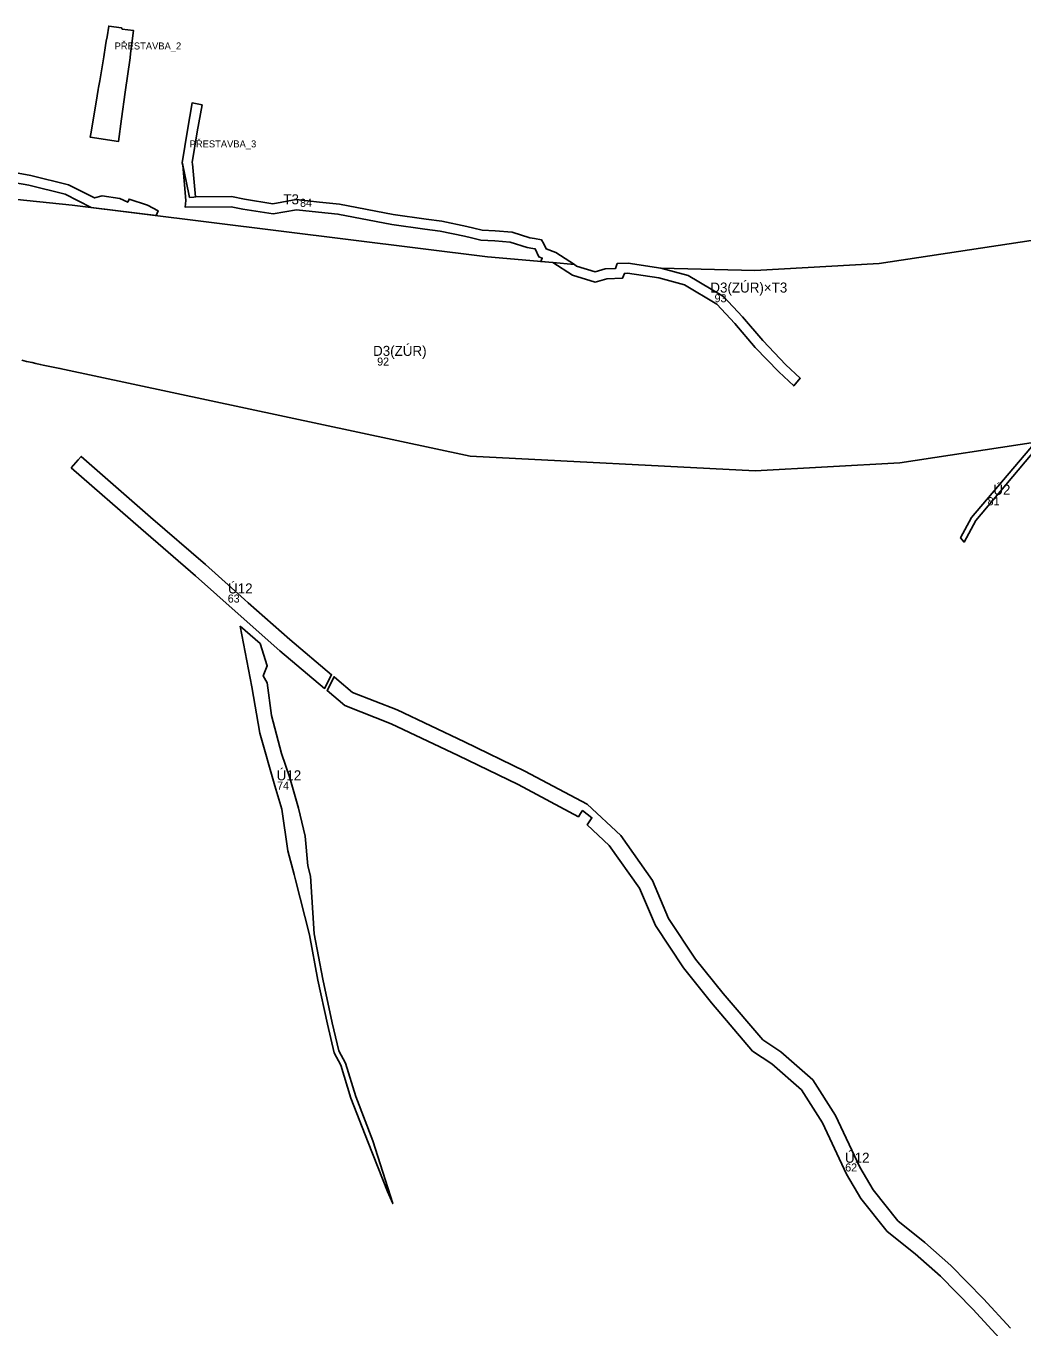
# Model space of a CAD drawing. Extents: x -521621 to -516857, y -1190025 to -1185894.
# Drawn here: x -519468 to -518471, y -1188636 to -1187334 of the extents above; entities that cross this region are included whole.
import ezdxf

# ---------------------------------------------------------------- set-up
doc = ezdxf.new("R2010")
doc.units = 0
for name, color, linetype in [('prestavba_n', 7, 'Continuous'), ('VPO_id', 7, 'Continuous'), ('VPO_n', 7, 'Continuous'), ('VPS_id', 7, 'Continuous'), ('VPS_n', 7, 'Continuous')]:
    doc.layers.add(name, color=color, linetype=linetype)

msp = doc.modelspace()

# ---------------------------------------------------------------- linework, layer by layer
at = {"layer": 'prestavba_n'}
for points in [[(-519368.5, -1187400.5), (-519363.8, -1187366.1), (-519363.3, -1187362), (-519363, -1187359.7), (-519360.2, -1187339), (-519371.6, -1187337.6), (-519372.3, -1187336.4), (-519385.1, -1187334.5), (-519386.8, -1187345.3), (-519387.5, -1187349.5), (-519388.2, -1187354), (-519390, -1187365.2), (-519391.3, -1187373.2), (-519394.1, -1187389.3), (-519395.2, -1187396), (-519395.6, -1187397.9), (-519396.7, -1187404.2), (-519402.6, -1187440.6), (-519403.5, -1187445.6), (-519375.2, -1187449.8), (-519372.2, -1187427.2), (-519368.5, -1187400.5)], [(-519311.7, -1187471.1), (-519311.4, -1187472.4), (-519311.1, -1187473.6), (-519307.7, -1187489.7), (-519304.3, -1187505.8), (-519299.9, -1187505.5), (-519298.2, -1187505.3), (-519301.2, -1187472.1), (-519301.5, -1187470.9), (-519296.5, -1187440.4), (-519291.8, -1187413.4), (-519301.7, -1187411.4), (-519306.3, -1187438.7), (-519311.7, -1187471.1)]]:
    msp.add_lwpolyline(points, dxfattribs=at)
at = {"layer": 'VPO_n'}
for points in [[(-518451.1, -1187749.3), (-518518.3, -1187828.7), (-518530, -1187850.3), (-518533.4, -1187846), (-518522.5, -1187825.9), (-518458.6, -1187750.5)], [(-519422.5, -1187776), (-519415.6, -1187768.2), (-519412.6, -1187764.7), (-519343.3, -1187825.6), (-519288.3, -1187872.8), (-519249.5, -1187907.6), (-519245.6, -1187911), (-519204.1, -1187947.8), (-519162.2, -1187983), (-519169.2, -1187996.7), (-519213.9, -1187959.1), (-519255.6, -1187922.2), (-519298.2, -1187884.1), (-519353.1, -1187836.9)], [(-519253.8, -1187934.5), (-519233.6, -1187951.8), (-519226.6, -1187973.9), (-519230.7, -1187984), (-519226.7, -1187990.9), (-519222.4, -1188023.6), (-519212.2, -1188061.6), (-519204, -1188086.1), (-519195.2, -1188116.4), (-519188.6, -1188144.5), (-519186.1, -1188173.9), (-519183.4, -1188184.3), (-519179.6, -1188242), (-519171.1, -1188287.2), (-519161.6, -1188331.1), (-519155.1, -1188358.9), (-519148.3, -1188371.3), (-519138.1, -1188404.6), (-519120.9, -1188448.8), (-519101.2, -1188511.7), (-519106.4, -1188499.6), (-519125.6, -1188450.6), (-519142.9, -1188406.3), (-519152.9, -1188373.2), (-519159.8, -1188360.8), (-519166.5, -1188332.2), (-519176, -1188288.2), (-519184.4, -1188243.1), (-519198.2, -1188188.1), (-519199.6, -1188182.6), (-519205.9, -1188159.1), (-519212.1, -1188117.2), (-519218.9, -1188094), (-519234, -1188041.5), (-519242, -1187995.2)]]:
    msp.add_lwpolyline(points, close=True, dxfattribs=at)
msp.add_lwpolyline([(-518494.6, -1188646.3), (-518521.3, -1188617.2), (-518553.6, -1188584.3), (-518578.9, -1188561.9), (-518606.8, -1188539.5), (-518633, -1188506.5), (-518647.5, -1188482.3), (-518671.6, -1188430.9), (-518692.6, -1188397.9), (-518722.2, -1188371.9), (-518741.4, -1188359.3), (-518782.4, -1188311.1), (-518810.5, -1188276.1), (-518838.6, -1188233.7), (-518854.5, -1188196.2), (-518884.6, -1188153.7), (-518906.7, -1188133.1), (-518902, -1188126), (-518906.7, -1188122.4), (-518911.4, -1188118.8), (-518913.4, -1188121.8), (-518915.5, -1188124.9), (-518975.8, -1188092.8), (-519035.8, -1188063.6), (-519102.8, -1188032), (-519149.1, -1188013.6), (-519166.7, -1187998.8), (-519159.8, -1187985), (-519159.6, -1187985.2), (-519157, -1187987.3), (-519141.3, -1188000.6), (-519096.8, -1188018.2), (-519029.3, -1188050.1), (-518969, -1188079.4), (-518906.7, -1188112.5), (-518873.2, -1188143.8), (-518841.3, -1188188.8), (-518825.3, -1188226.5), (-518798.4, -1188267.3), (-518770.9, -1188301.6), (-518731.3, -1188347.9), (-518713.1, -1188360), (-518681.1, -1188388), (-518658.4, -1188423.7), (-518634.3, -1188475.2), (-518620.7, -1188498), (-518596.1, -1188528.9), (-518569.2, -1188550.4), (-518543.2, -1188573.4), (-518510.4, -1188606.8), (-518483.5, -1188636.3)], dxfattribs=at)
at = {"layer": 'VPS_n'}
for points in [[(-519306.3, -1187438.7), (-519301.7, -1187411.4), (-519291.8, -1187413.4), (-519296.5, -1187440.4), (-519301.5, -1187470.9), (-519301.2, -1187472.1), (-519298.2, -1187505.3), (-519262.5, -1187504.9), (-519249.3, -1187507.6), (-519220.9, -1187512.2), (-519197.7, -1187508), (-519174.4, -1187510.5), (-519154.5, -1187512.6), (-519100.6, -1187523), (-519067.6, -1187527.6), (-519052.2, -1187529.7), (-519027.2, -1187534.9), (-519020.2, -1187536.4), (-519011.6, -1187538.6), (-518998.6, -1187539.3), (-518981.7, -1187540.5), (-518964.2, -1187546.2), (-518959.5, -1187546.9), (-518952.3, -1187548.3), (-518950, -1187552.2), (-518947.7, -1187557.3), (-518938.1, -1187561), (-518919.5, -1187573), (-518941, -1187571), (-518953.1, -1187569.9), (-518951.6, -1187566.5), (-518955.2, -1187565.1), (-518958.7, -1187557.3), (-518961.2, -1187556.8), (-518966.6, -1187556), (-518983.6, -1187550.4), (-518999.2, -1187549.3), (-519013.1, -1187548.5), (-519022.5, -1187546.1), (-519029.3, -1187544.6), (-519053.8, -1187539.6), (-519069, -1187537.5), (-519102.2, -1187532.8), (-519155.9, -1187522.5), (-519175.4, -1187520.4), (-519197.3, -1187518.1), (-519220.8, -1187522.3), (-519251.1, -1187517.4), (-519262.7, -1187515.1), (-519308.7, -1187515.4), (-519307.9, -1187508.8), (-519311.1, -1187473.6), (-519311.7, -1187471.1)], [(-518941, -1187571), (-518919.5, -1187573), (-518917.3, -1187574.4), (-518898.7, -1187580.1), (-518888.6, -1187577.2), (-518878.4, -1187576.7), (-518876.6, -1187571.9), (-518865.7, -1187571.6), (-518833.1, -1187576.5), (-518805.7, -1187584), (-518770.6, -1187604.7), (-518751.6, -1187625.3), (-518731.3, -1187649), (-518708, -1187673), (-518693.8, -1187686.5), (-518700.2, -1187694.3), (-518715.1, -1187680.2), (-518738.7, -1187655.7), (-518759, -1187631.9), (-518777, -1187612.5), (-518809.6, -1187593.3), (-518835.2, -1187586.3), (-518866.3, -1187581.6), (-518869.6, -1187581.7), (-518871.3, -1187586.4), (-518887, -1187587.1), (-518898.8, -1187590.5), (-518921.5, -1187583.6)]]:
    msp.add_lwpolyline(points, close=True, dxfattribs=at)
for points in [[(-519790.9, -1187475.7), (-519421.5, -1187513.5), (-519006.3, -1187565.1), (-518941, -1187571), (-518921.5, -1187583.6), (-518898.8, -1187590.5), (-518887, -1187587.1), (-518871.3, -1187586.4), (-518869.6, -1187581.7), (-518866.3, -1187581.6), (-518835.2, -1187586.3), (-518809.6, -1187593.3), (-518777, -1187612.5), (-518759, -1187631.9), (-518738.7, -1187655.7), (-518715.1, -1187680.2), (-518700.2, -1187694.3), (-518693.8, -1187686.5), (-518708, -1187673), (-518731.3, -1187649), (-518751.6, -1187625.3), (-518770.6, -1187604.7), (-518805.7, -1187584), (-518833.1, -1187576.5), (-518739, -1187578.8), (-518614.8, -1187572), (-518434.3, -1187544.5)], [(-519475.7, -1187481.4), (-519462.8, -1187483.9), (-519425.3, -1187493.2), (-519399.3, -1187506.3), (-519391.7, -1187504.3), (-519374.1, -1187506.8), (-519366.1, -1187510.6), (-519364.7, -1187507.5), (-519346.2, -1187513.6), (-519335.5, -1187519.3), (-519337.5, -1187523.9), (-519402.5, -1187515.9), (-519428.8, -1187502.6), (-519465, -1187493.7), (-519478.4, -1187491.1)], [(-518458.6, -1187750.5), (-518594.2, -1187771.1), (-518738.7, -1187779), (-519023.8, -1187764.4), (-519433.9, -1187676.7), (-519450.5, -1187673.5), (-519453.5, -1187672.8), (-519458, -1187671.8), (-519461.7, -1187670.9), (-519467.2, -1187669.7), (-519472.1, -1187668.6)]]:
    msp.add_lwpolyline(points, dxfattribs=at)

# ---------------------------------------------------------------- texts
at = {"layer": 'prestavba_n'}
for s, p in [('PŘESTAVBA_2', (-519379.2, -1187357.9)), ('PŘESTAVBA_3', (-519304.2, -1187455.8))]:
    msp.add_text(s, height=7, dxfattribs=at).set_placement(p)
at = {"layer": 'VPO_id'}
for s, p in [('81', (-518506.4, -1187813.5)), ('63', (-519266.1, -1187910.8)), ('74', (-519216.7, -1188097.7)), ('62', (-518648.8, -1188479.5))]:
    msp.add_text(s, height=8, dxfattribs=at).set_placement(p)
at = {"layer": 'VPO_n'}
for s, p in [('Ú2', (-518500.7, -1187803.1)), ('Ú12', (-519265.8, -1187901.7)), ('Ú12', (-519217.2, -1188088.5)), ('Ú12', (-518649, -1188470.8))]:
    msp.add_text(s, height=10, dxfattribs=at).set_placement(p)
at = {"layer": 'VPS_id'}
for s, p in [('84', (-519193.8, -1187515.2)), ('93', (-518779.4, -1187610.6)), ('92', (-519116.7, -1187673.9))]:
    msp.add_text(s, height=8, dxfattribs=at).set_placement(p)
at = {"layer": 'VPS_n'}
for s, p in [('T3', (-519210.5, -1187512.7)), ('D3(ZÚR)×T3', (-518783.6, -1187600.9)), ('D3(ZÚR)', (-519120.8, -1187664.2))]:
    msp.add_text(s, height=10, dxfattribs=at).set_placement(p)

doc.saveas('drawing.dxf')
